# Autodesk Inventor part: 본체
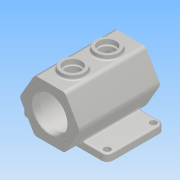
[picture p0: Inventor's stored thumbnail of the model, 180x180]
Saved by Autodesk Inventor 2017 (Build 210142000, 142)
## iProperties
Part Number: 본체
Material: 알루미늄 6061
Document SubType Name: Modeling
Designer: user
Density: 2.7 g/cm^3
Appearance: 알루미늄 - 평지
Author: user
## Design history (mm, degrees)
sketch "스케치1"
  geometry: L1 (-50, 75)-(50, 75); L2 (50, 75)-(50, -75); L3 (50, -75)-(-50, -75); L4 (-50, -75)-(-50, 75); L5 (-50, 75)-(50, -75); L6 (50, 75)-(-50, -75); 1 further point
  constraints: 12 end point, 2 midpoint, 2 parallel, 1 horizontal, 1 perpendicular
  dimensions: "d0" = 100 distance of L2.end L3.end; "d1" = 150 distance of L3.end L1.start
extrude "돌출1" new body sketch "스케치1" distance "d2" = 12; taper "d3" = 0 deg
sketch "스케치3" dims "d5" = 105
  geometry: L1 (75, 0)-(-75, 0) reference; L2 (52.5, 50)-(26.25, 4.534); L3 (26.25, 4.534)-(-26.25, 4.534); L4 (-26.25, 4.534)-(-52.5, 50); L5 (-52.5, 50)-(-26.25, 95.466); L6 (-26.25, 95.466)-(26.25, 95.466); L7 (26.25, 95.466)-(52.5, 50); 3 further points
  constraints: 12 end point, 1 coincident, 1 horizontal alignment, 15 other
  dimensions: "d4" = 50 distance from line of L1 point (0, 50)
extrude "돌출2" join sketch "스케치3" distance "d6" = 75; taper "d8" = 0 deg; dims "d7" = 65, "d9" = 0
sketch "스케치4"
  geometry: L1 (-95.466, -26.25)-(-4.534, 26.25); C1 r 30 at (-50, 0); 1 further point
  constraints: 2 end point, 1 centre point, 1 midpoint
  dimensions: "d10" = 60 diameter of C1
extrude "돌출3" cut sketch "스케치4" distance "d11" = 186.25; taper "d12" = 0 deg
sketch "스케치5"
  geometry: L1 (-50, 0)-(-78.284, 28.284); L2 (-50, 0)-(-50, 40); C1 r 30 at (-50, 0) reference; A1 r 40 centre (-50, 0) between (-78.284, 28.284) and (-50, 40); 2 further points
  constraints: 4 end point, 2 coincident, 2 point on circle, 1 centre point, 1 vertical alignment
  dimensions: "d13" = 80 diameter of A1; "d14" = 45 deg angle of L2 L1
hole "구멍1" sketch "스케치5" at (-78.284, 28.284) diameter "d15" = 3.242; stored, may be unused: countersink angle "d19" = 90 deg, drill point angle "d21" = 118 deg; dims "d16" = 8, "d17" = 4, "d18" = 2, "d20" = 10
sketch "스케치6" dims "d25" = 80
  geometry: L1 (50, 0)-(90, 0); C1 r 30 at (50, 0) reference; 2 further points
  constraints: 2 coincident, 2 end point, 1 horizontal, 1 horizontal alignment, 2 other
hole "구멍2" sketch "스케치6" at (90, 0) diameter "d26" = 3.242; stored, may be unused: countersink angle "d30" = 90 deg, drill point angle "d32" = 118 deg; dims "d27" = 8, "d28" = 4, "d29" = 2, "d31" = 10
fillet "모깎기1" dims "d36" = 10
hole "구멍3" diameter "d39" = 11; stored, may be unused: countersink angle "d43" = 90 deg, drill point angle "d45" = 0 deg; dims "d37" = 10, "d38" = 10, "d40" = 10, "d41" = 4, "d42" = 2, "d44" = 30
hole "구멍4" diameter "d48" = 11; stored, may be unused: countersink angle "d52" = 90 deg, drill point angle "d54" = 0 deg; dims "d46" = 10, "d47" = 10, "d49" = 10, "d50" = 4, "d51" = 2, "d53" = 30
hole "구멍5" diameter "d57" = 11; stored, may be unused: countersink angle "d61" = 90 deg, drill point angle "d63" = 0 deg; dims "d55" = 10, "d56" = 10, "d58" = 10, "d59" = 4, "d60" = 2, "d62" = 30
hole "구멍6" diameter "d66" = 11; stored, may be unused: countersink angle "d70" = 90 deg, drill point angle "d72" = 0 deg; dims "d64" = 10, "d65" = 10, "d67" = 10, "d68" = 4, "d69" = 2, "d71" = 30
node "작업 평면1"
sketch "스케치8"
  geometry: L1 (75, 26.25)-(75, -26.25) reference; C1 r 20 at (35, 0); C2 r 20 at (-25, 0); 1 further point
  constraints: 2 centre point, 2 horizontal alignment
  dimensions: "d76" = 40 diameter of C1; "d77" = 40 diameter of C2; "d78" = 40 distance from line of C1.centre L1; "d79" = 60 distance of C2.centre C1.centre
extrude "돌출4" join sketch "스케치8" stored distance "d80" = 186.25; taper "d81" = 0 deg
sketch "스케치9"
  geometry: C1 r 20 at (0, 0) reference; C2 r 15 at (0, 0); 1 further point
  constraints: 1 centre point, 1 coincident
  dimensions: "d82" = 30 diameter of C2
extrude "돌출5" cut sketch "스케치9" distance "d83" = 8; taper "d84" = 0 deg
sketch "스케치10"
  geometry: C1 r 15 at (0, 0) reference; C2 r 12.5 at (0, 0); 1 further point
  constraints: 1 centre point, 1 coincident
  dimensions: "d85" = 25 diameter of C2
extrude "돌출6" cut sketch "스케치10" distance "d86" = 40; taper "d87" = 0 deg
sketch "스케치11"
  geometry: C1 r 20 at (0, 0) reference; C2 r 15 at (0, 0); 1 further point
  constraints: 1 centre point, 1 coincident
  dimensions: "d88" = 30 diameter of C2
extrude "돌출7" cut sketch "스케치11" distance "d89" = 8; taper "d90" = 0 deg
sketch "스케치12"
  geometry: C1 r 15 at (0, 0) reference; C2 r 12.5 at (0, 0); 1 further point
  constraints: 1 centre point, 1 coincident
  dimensions: "d91" = 25 diameter of C2
extrude "돌출8" cut sketch "스케치12" distance "d92" = 40.75; taper "d93" = 0 deg
chamfer "모따기1" distance "d94" = 1; stored, may be unused: second distance "d95" = 2, angle "d96" = 45 deg
sketch "스케치13"
  geometry: L1 (-75, 20)-(-75, 80) reference; L2 (65, 80)-(65, 20) reference; L3 (-75, 50)-(65, 50); L4 (-75, 80)-(65, 80) reference; L5 (-63, 80)-(-63, 87.5); L6 (-63, 87.5)-(53, 87.5); L7 (53, 87.5)-(53, 80); L8 (-75, 95.466)-(-75, 50) reference; L9 (65, 50)-(65, 95.466) reference; 1 further point
  constraints: 8 end point, 2 midpoint, 2 point on line, 1 parallel, 1 perpendicular, 1 vertical
  dimensions: "d97" = 75 diameter of L6 L3; "d98" = 12 distance between parallel lines of L5 L8; "d99" = 12 distance between parallel lines of L9 L7
revolve "회전1" sketch "스케치13" stored, may be unused: angle "d100" = 90 deg
fillet "모깎기2" dims "d101" = 8
fillet "모깎기3" dims "d102" = 5
chamfer "모따기2" distance "d103" = 1; stored, may be unused: second distance "d104" = 2, angle "d105" = 45 deg
fillet "모깎기4" dims "d106" = 3
fillet "모깎기5" dims "d107" = 3
fillet "모깎기6" dims "d108" = 3
sketch "스케치14"
  geometry: L1 (40, -72)-(-40, -72) reference; L2 (-20.739, -57.998)-(20.739, -57.998); L3 (20.739, -57.998)-(20.739, -64.002); L4 (20.739, -64.002)-(-20.739, -64.002); L5 (-20.739, -64.002)-(-20.739, -57.998); L6 (-20.739, -57.998)-(20.739, -64.002); L7 (-40, -75)-(40, -75) reference; L8 (50, -65)-(50, -35.757) reference; 3 further points
  constraints: 2 end point, 2 midpoint, 1 vertical alignment, 2 other
  dimensions: "d109" = 14 distance from line of L7 point (0, -61); "d110" = 50 distance from line of L8 point (0, -61) (derived)
extrude "돌출9" cut sketch "스케치14" distance "d111" = 0.5; taper "d112" = 0 deg
node "솔리드1"
pattern_circular "원형 패턴1" dims angle "d23" = 360 deg
pattern_circular "원형 패턴2" dims angle "d34" = 360 deg
other parameters: "d75" = 102.5
